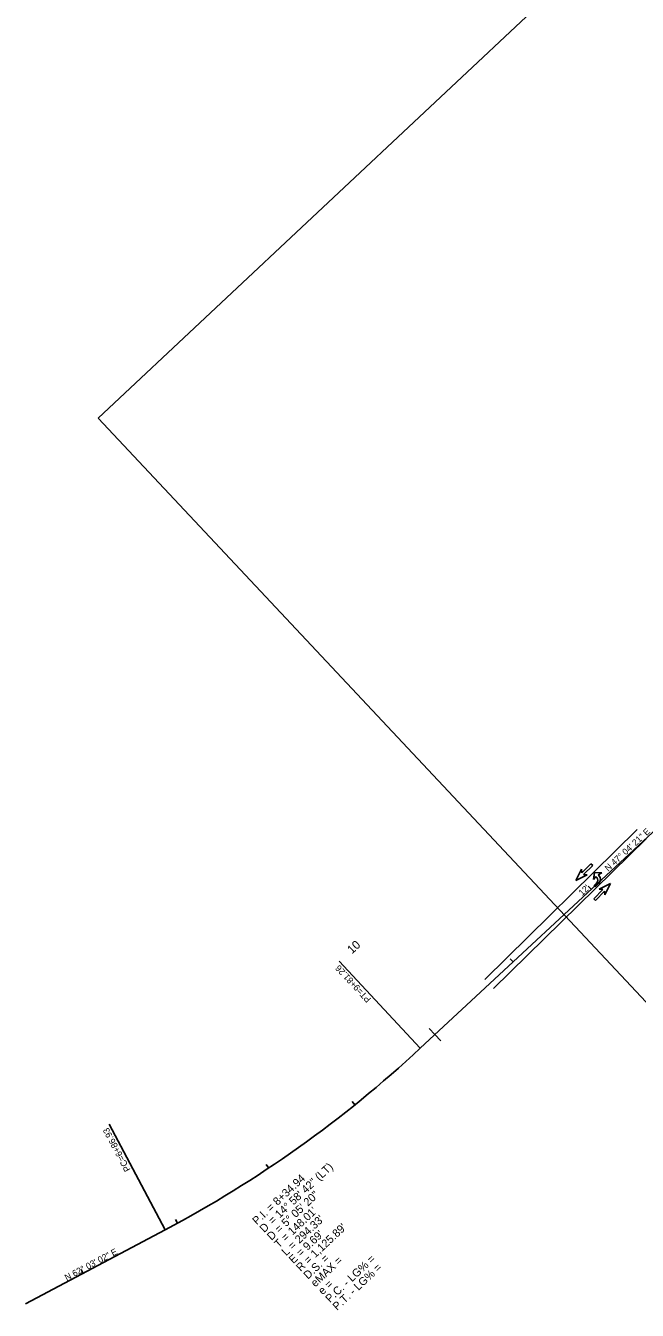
# Model space of a CAD drawing. Extents: x 1623239 to 1625698, y 1118659 to 1120751.
# Drawn here: x 1623239 to 1623812, y 1118659 to 1119863 of the extents above; entities that cross this region are included whole.
import ezdxf

# ---------------------------------------------------------------- set-up
doc = ezdxf.new("R2010")
doc.units = 0
for name, color, linetype in [('Default', 7, 'Continuous'), ('RD_HC_Cl', 7, 'Continuous'), ('RD_HC_Data', 7, 'Continuous'), ('RD_HC_Data_Tic', 7, 'Continuous'), ('RD_HC_TX_Sta50', 7, 'Continuous'), ('RD_PD_Final_LnLine', 7, 'Continuous'), ('RD_PD_Final_TX', 7, 'Continuous'), ('RD_PD_PaintMed', 7, 'Continuous'), ('RD_PD_RW_TX', 7, 'Continuous'), ('RD_SHT_ShtClip', 7, 'Continuous')]:
    doc.layers.add(name, color=color, linetype=linetype)

# ---------------------------------------------------------------- blocks, each defined once
blk = doc.blocks.new('TARROW')
at = {"layer": 'RD_PD_Final_LnLine'}
for p, q in [((-3.3, -5.34), (-5.38, -5.34)), ((-5.38, -5.34), (-5.38, -6.34)), ((-5.38, -6.34), (-2.63, -6.34)), ((-3.29, -2.67), (-1.05, -2.34)), ((-1.05, -2.34), (-1.05, -3.09)), ((0.62, -3.09), (0.62, -2.5)), ((0.62, -2.5), (2.87, -3.17))]:
    blk.add_line(p, q, dxfattribs=at)
blk.add_lwpolyline([(2.87, -3.17), (0, 0), (-3.29, -2.67)], dxfattribs=at)
for centre, radius in [((-3.3, -3.09), 2.25), ((-2.63, -3.09), 3.25)]:
    blk.add_arc(centre, radius, 270, 0, dxfattribs=at)
blk = doc.blocks.new('RA Curved')
at = {"layer": 'RD_PD_Final_LnLine', "xscale": 1.0799984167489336, "yscale": -1.0799984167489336}
blk.add_blockref('TARROW', (6.14, -5.79), dxfattribs=at)

msp = doc.modelspace()

# ---------------------------------------------------------------- linework, layer by layer
at = {"layer": 'Default'}
msp.add_line((1623622.6, 1118917.1), (1623617.1, 1118922.9), dxfattribs=at)
at = {"layer": 'RD_HC_Cl'}
for p, q in [((1623608.8, 1118904.3), (1623937.2, 1119209.8)), ((1623239, 1118664.8), (1623369.7, 1118734.1))]:
    msp.add_line(p, q, dxfattribs=at)
msp.add_arc((1622842, 1119728.7), 1125.9, 297.9494, 312.9276, dxfattribs=at)
at = {"layer": 'RD_HC_Data'}
for p, q in [((1623608.8, 1118904.3), (1623532.9, 1118986)), ((1623369.7, 1118734.1), (1623317.2, 1118833.1))]:
    msp.add_line(p, q, dxfattribs=at)
at = {"layer": 'RD_HC_Data_Tic'}
for p, q in [((1623769, 1119053.3), (1623766.3, 1119056.2)), ((1623695.8, 1118985.2), (1623693.1, 1118988.1)), ((1623622.6, 1118917.1), (1623617.1, 1118922.9)), ((1623622.6, 1118917.1), (1623628, 1118911.2)), ((1623547.4, 1118851.2), (1623544.9, 1118854.3)), ((1623466.8, 1118792.1), (1623464.5, 1118795.4)), ((1623381.2, 1118740.3), (1623379.3, 1118743.8)), ((1623292.9, 1118693.4), (1623291, 1118696.9))]:
    msp.add_line(p, q, dxfattribs=at)
at = {"layer": 'RD_PD_Final_TX'}
for p, q in [((1623760, 1119072), (1623754.7, 1119061.4)), ((1623754.7, 1119061.4), (1623765.2, 1119066.8)), ((1623760.3, 1119068.7), (1623760, 1119072)), ((1623768.8, 1119077.2), (1623760.3, 1119068.7)), ((1623761.9, 1119067.1), (1623770.4, 1119075.7)), ((1623765.2, 1119066.8), (1623761.9, 1119067.1)), ((1623770.4, 1119075.7), (1623768.8, 1119077.2)), ((1623787.1, 1119058.8), (1623776.6, 1119053.3)), ((1623781.9, 1119048.2), (1623787.1, 1119058.8)), ((1623779.9, 1119053), (1623771.5, 1119044.5)), ((1623771.5, 1119044.5), (1623773.1, 1119042.9)), ((1623773.1, 1119042.9), (1623781.5, 1119051.4)), ((1623776.6, 1119053.3), (1623779.9, 1119053)), ((1623781.5, 1119051.4), (1623781.9, 1119048.2))]:
    msp.add_line(p, q, dxfattribs=at)
at = {"layer": 'RD_PD_PaintMed'}
for p, q in [((1623669.2, 1118968.8), (1623812.2, 1119109.2)), ((1623677.6, 1118960.2), (1623820.5, 1119100.5))]:
    msp.add_line(p, q, dxfattribs=at)
at = {"layer": 'RD_SHT_ShtClip'}
for p, q in [((1623307.1, 1119494.9), (1624620.1, 1120726.2)), ((1624059.6, 1118692.6), (1623307.1, 1119494.9))]:
    msp.add_line(p, q, dxfattribs=at)

# ---------------------------------------------------------------- block references
at = {"layer": 'RD_PD_RW_TX', "xscale": 1.5, "yscale": -1.4999999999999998, "rotation": 43.162669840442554}
msp.add_blockref('RA Curved', (1623771.3, 1119056.5), dxfattribs=at)

# ---------------------------------------------------------------- texts
at = {"layer": 'RD_HC_Data'}
for s, height, rotation, p in [('N 47%%d 04\' 21" E', 6, 42.9276, (1623785, 1119069.7)), ('PT=9+81.26', 6, 132.9276, (1623563.1, 1118950.6)), ('PC=6+86.93', 6, 117.9494, (1623337.5, 1118790.6)), ('    = 14%%d 58\' 42" (LT)', 7.5, 43.1627, (1623462.5, 1118731.1)), ('P.I. = 8+34.94', 7.5, 43.1627, (1623455.7, 1118738.4)), ('D = 5%%d 05\' 20"', 7.5, 43.1627, (1623469.4, 1118723.8)), ("T = 148.01'", 7.5, 43.1627, (1623476.2, 1118716.6)), ("L = 294.33'", 7.5, 43.1627, (1623483.1, 1118709.3)), ('D', 7.5, 43.1627, (1623462.5, 1118731.1)), ("E = 9.69'", 7.5, 43.1627, (1623489.9, 1118702)), ("R = 1,125.89'", 7.5, 43.1627, (1623496.7, 1118694.7)), ('N 62%%d 03\' 02" E', 6, 27.9494, (1623277.5, 1118686.3)), ('D.S. = ', 7.5, 43.1627, (1623503.6, 1118687.4)), ('eMAX = ', 7.5, 43.1627, (1623510.4, 1118680.1)), ('P.C. - LG% = ', 7.5, 43.1627, (1623524.1, 1118665.5)), ('P.T. - LG% = ', 7.5, 43.1627, (1623530.9, 1118658.2)), ('e = ', 7.5, 43.1627, (1623517.3, 1118672.8))]:
    msp.add_text(s, height=height, rotation=rotation, dxfattribs=at).set_placement(p)
at = {"layer": 'RD_HC_TX_Sta50'}
msp.add_text('10', height=8, rotation=42.9276, dxfattribs=at).set_placement((1623544.8, 1118992.2))
at = {"layer": 'RD_PD_Final_TX'}
msp.add_text("12'", height=6, rotation=43.1619, dxfattribs=at).set_placement((1623760.6, 1119046.7))

doc.saveas('drawing.dxf')
